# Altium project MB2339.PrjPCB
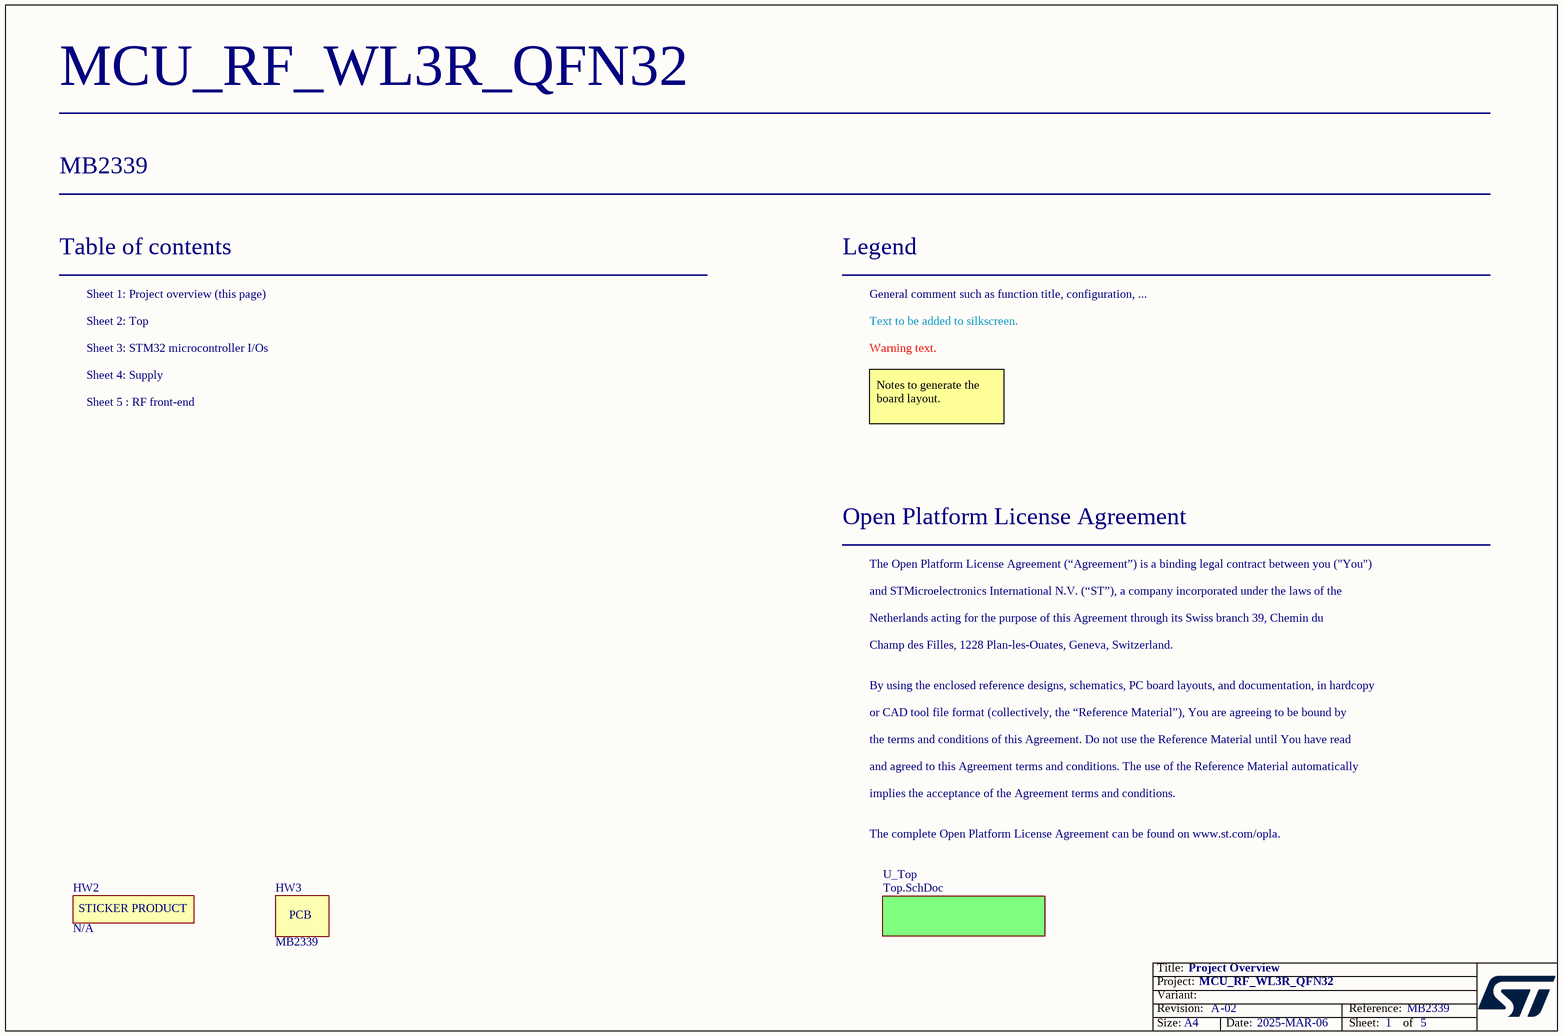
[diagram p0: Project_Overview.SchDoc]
Board_Assembly_Revision: 02; Board_Document_Date: 2025-MAR-06; Board_Name: MCU_RF_WL3R_QFN32; Board_PCB_Revision: A; Board_Reference: MB2339
5 sheets, 95 parts. Net scope: flat (ports and power ports of the same name join across sheets).
Board file: MB2339.PcbDoc
Sheets:
  Project_Overview.SchDoc
    U_Top = Top.SchDoc
      Designator = MCU_IOs.SchDoc
      Designator = RF.SchDoc
      Designator = Supply.SchDoc

## Sheet Project_Overview.SchDoc: Project Overview
size A4; Date: Not used; ApprovedBy: Not used; CheckedBy: Not used; Author: Not used; CompanyName: STMicroelectronics; DrawnBy: Not used; Engineer: Not used; Organization: Not used; Address1: Not used; Address2: Not used; Address3: Not used; Address4: Not used; DocumentNumber: 1; Revision: Not used; SheetNumber: 1; SheetTotal: 5

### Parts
HW2  STICKER_PRODUCT  [STICKER_PRODUCT_25X9]  (value not drawn)  (no BOM)
HW3  value MB2339  (hidden comment: PCB)

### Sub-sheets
U_Top = Top.SchDoc: no entries

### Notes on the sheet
- Table of contents
- Sheet 1: Project overview (this page)
- Legend
- General comment such as function title, configuration, ...
- Sheet 2: Top
- Sheet 3: STM32 microcontroller I/Os
- Sheet 4: Supply
- Text to be added to silkscreen.
- Warning text.
- Sheet 5 : RF front-end
- Notes to generate the board layout.
- Open Platform License Agreement
- The Open Platform License Agreement (“Agreement”) is a binding legal contract between you ("You")
- and STMicroelectronics International N.V. (“ST”), a company incorporated under the laws of the
- Netherlands acting for the purpose of this Agreement through its Swiss branch 39, Chemin du
- Champ des Filles, 1228 Plan-les-Ouates, Geneva, Switzerland.
- By using the enclosed reference designs, schematics, PC board layouts, and documentation, in hardcopy
- or CAD tool file format (collectively, the “Reference Material”), You are agreeing to be bound by
- the terms and conditions of this Agreement. Do not use the Reference Material until You have read
- and agreed to this Agreement terms and conditions. The use of the Reference Material automatically
- implies the acceptance of the Agreement terms and conditions.
- The complete Open Platform License Agreement can be found on www.st.com/opla.

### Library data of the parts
HW2 = MCD-00547: Sticker product, 25x9mm; Part_Type: Misc; Part_Preference: Recommended; Component_Country_Of_Origin: Unknown; ShowFields: YES; ID: 3197
HW3 = MCD-04477: PCB, MB2339, STM32WL3R Nucleo, 4L2S; Part_Preference: Recommended; Manufacturer: WURTH ELEKTRONIK; Component_Country_Of_Origin: Unknown; ShowFields: YES; ID: 6593

## Sheet Top.SchDoc: Top Schematic
size A4; Date: Not used; ApprovedBy: Not used; CheckedBy: Not used; Author: Not used; CompanyName: STMicroelectronics; DrawnBy: Not used; Engineer: Not used; Organization: Not used; Address1: Not used; Address2: Not used; Address3: Not used; Address4: Not used; DocumentNumber: 2; Revision: Not used; SheetNumber: 2; SheetTotal: 5
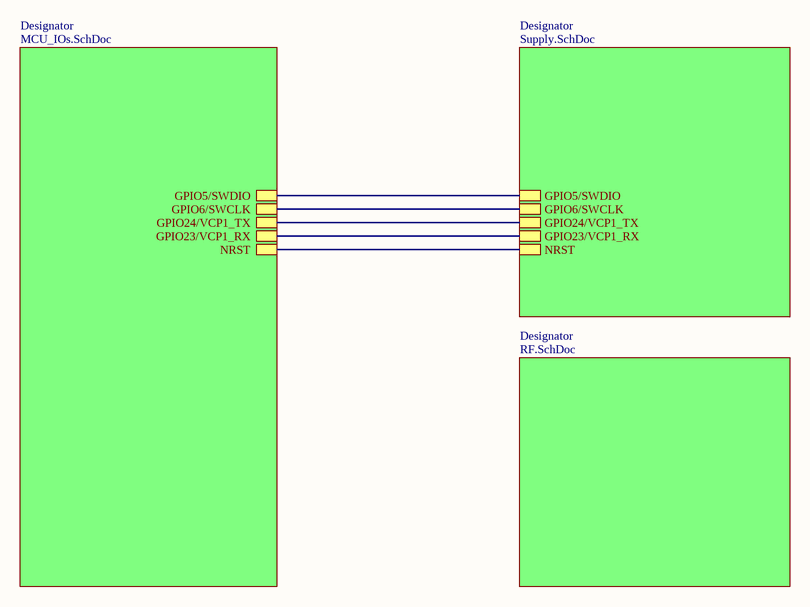
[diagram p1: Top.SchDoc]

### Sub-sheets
Designator = MCU_IOs.SchDoc: NRST, GPIO5/SWDIO, GPIO6/SWCLK, GPIO24/VCP1_TX, GPIO23/VCP1_RX
Designator = RF.SchDoc: no entries
Designator = Supply.SchDoc: NRST, GPIO5/SWDIO, GPIO6/SWCLK, GPIO23/VCP1_RX, GPIO24/VCP1_TX

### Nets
(unnamed): sheet Designator/NRST, sheet Designator/NRST
(unnamed): sheet Designator/GPIO5/SWDIO, sheet Designator/GPIO5/SWDIO  [a separate net that carries the same name]
(unnamed): sheet Designator/GPIO6/SWCLK, sheet Designator/GPIO6/SWCLK  [a separate net that carries the same name]
(unnamed): sheet Designator/GPIO24/VCP1_TX, sheet Designator/GPIO24/VCP1_TX  [a separate net that carries the same name]
(unnamed): sheet Designator/GPIO23/VCP1_RX, sheet Designator/GPIO23/VCP1_RX  [a separate net that carries the same name]

## Sheet MCU_IOs.SchDoc: STM32 I/Os & Clock
size A4; Date: Not used; ApprovedBy: Not used; CheckedBy: Not used; Author: Not used; CompanyName: STMicroelectronics; DrawnBy: Not used; Engineer: Not used; Organization: Not used; Address1: Not used; Address2: Not used; Address3: Not used; Address4: Not used; DocumentNumber: 3; Revision: Not used; SheetNumber: 3; SheetTotal: 5
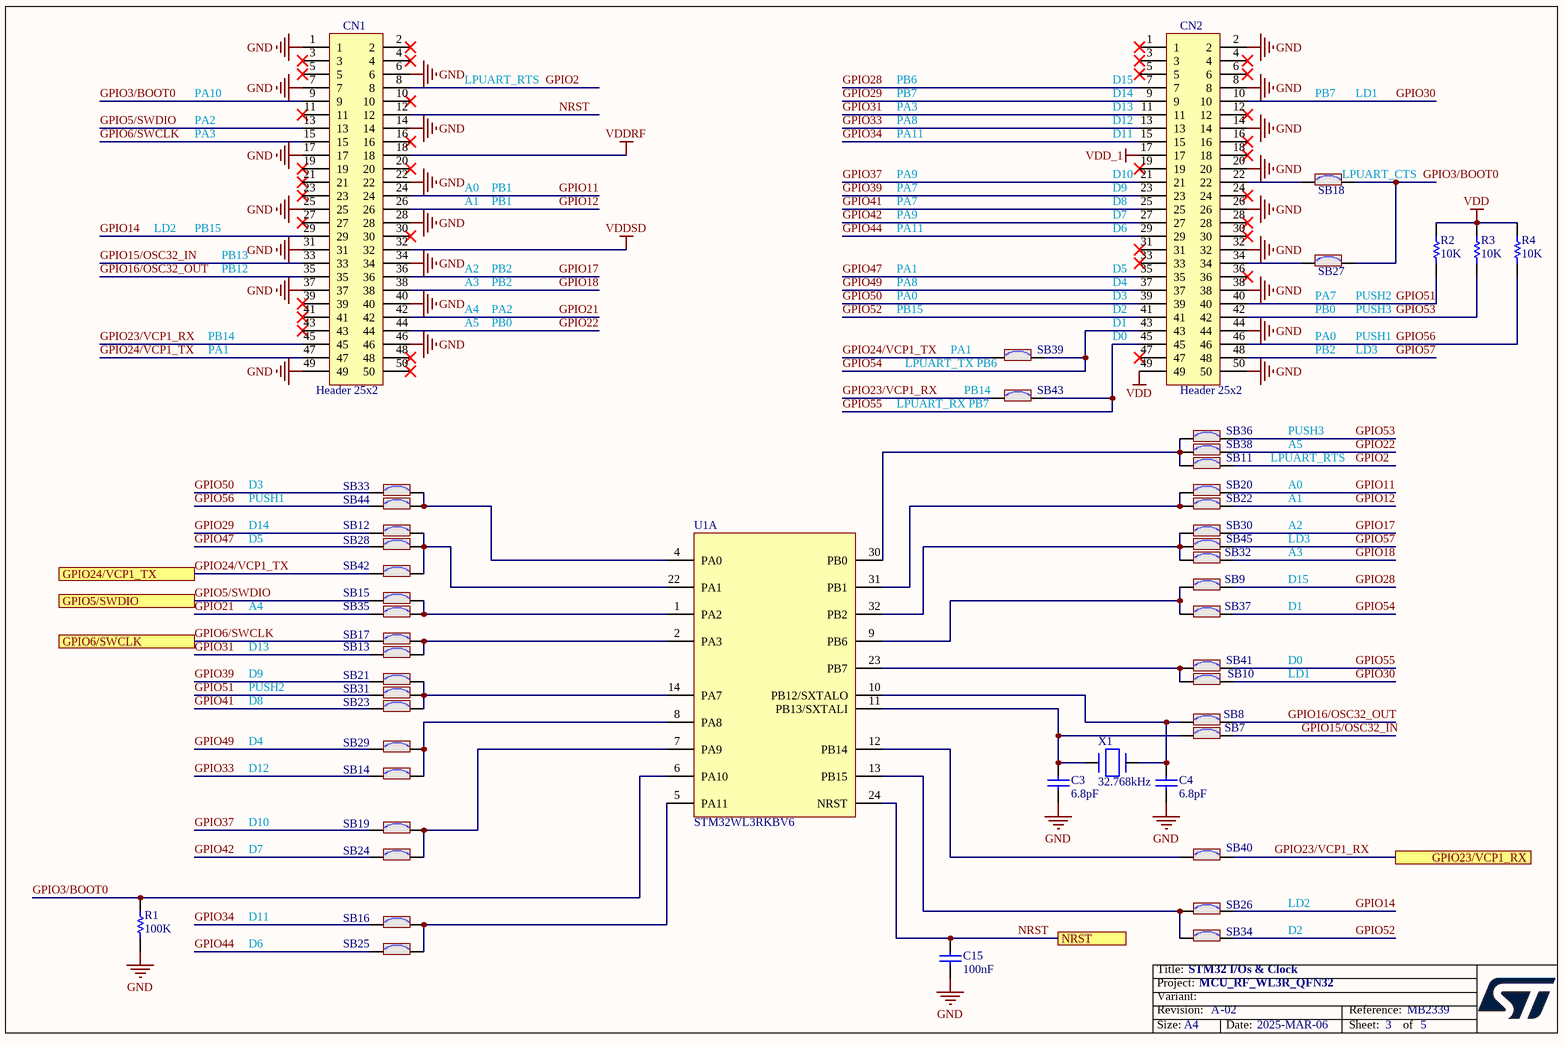
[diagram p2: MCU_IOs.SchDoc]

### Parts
C3  value 6.8pF  [C0402]  (hidden comment: Capacitor)
C4  value 6.8pF  [C0402]  (hidden comment: Capacitor)
C15  value 100nF  [C0402]  (hidden comment: Capacitor)
CN1  Header 25x2  [CON_SAMTEC_FTSH-125-02-L-DV]
CN2  Header 25x2  [CON_SAMTEC_FTSH-125-02-L-DV]
R1  value 100K  [R0402]  (hidden comment: Resistor)
R2  value 10K  [R0402]  (hidden comment: Resistor)
R3  value 10K  [R0402]  (hidden comment: Resistor)
R4  value 10K  [R0402]  (hidden comment: Resistor)
SB7  SB_ON  [SOLDER-BRIDGE_R0402-0R]  (value not drawn)
SB8  SB_ON  [SOLDER-BRIDGE_R0402-0R]  (value not drawn)
SB9  SB_ON  [SOLDER-BRIDGE_R0402-0R]  (value not drawn)
SB10  SB_ON  [SOLDER-BRIDGE_R0402-0R]  (value not drawn)
SB11  SB_ON  [SOLDER-BRIDGE_R0402-0R]  (value not drawn)
SB12  SB_ON  [SOLDER-BRIDGE_R0402-0R]  (value not drawn)
SB13  SB_ON  [SOLDER-BRIDGE_R0402-0R]  (value not drawn)
SB14  SB_ON  [SOLDER-BRIDGE_R0402-0R]  (value not drawn)
SB15  SB_ON  [SOLDER-BRIDGE_R0402-0R]  (value not drawn)
SB16  SB_ON  [SOLDER-BRIDGE_R0402-0R]  (value not drawn)
SB17  SB_ON  [SOLDER-BRIDGE_R0402-0R]  (value not drawn)
SB18  SB_ON  [SOLDER-BRIDGE_R0402-0R]  (value not drawn)
SB19  SB_ON  [SOLDER-BRIDGE_R0402-0R]  (value not drawn)
SB20  SB_ON  [SOLDER-BRIDGE_R0402-0R]  (value not drawn)
SB21  SB_ON  [SOLDER-BRIDGE_R0402-0R]  (value not drawn)
SB22  SB_ON  [SOLDER-BRIDGE_R0402-0R]  (value not drawn)
SB23  SB_ON  [SOLDER-BRIDGE_R0402-0R]  (value not drawn)
SB24  SB_ON  [SOLDER-BRIDGE_R0402-0R]  (value not drawn)
SB25  SB_ON  [SOLDER-BRIDGE_R0402-0R]  (value not drawn)
SB26  SB_ON  [SOLDER-BRIDGE_R0402-0R]  (value not drawn)
SB27  SB_ON  [SOLDER-BRIDGE_R0402-0R]  (value not drawn)
SB28  SB_ON  [SOLDER-BRIDGE_R0402-0R]  (value not drawn)
SB29  SB_ON  [SOLDER-BRIDGE_R0402-0R]  (value not drawn)
SB30  SB_ON  [SOLDER-BRIDGE_R0402-0R]  (value not drawn)
SB31  SB_ON  [SOLDER-BRIDGE_R0402-0R]  (value not drawn)
SB32  SB_ON  [SOLDER-BRIDGE_R0402-0R]  (value not drawn)
SB33  SB_ON  [SOLDER-BRIDGE_R0402-0R]  (value not drawn)
SB34  SB_ON  [SOLDER-BRIDGE_R0402-0R]  (value not drawn)
SB35  SB_ON  [SOLDER-BRIDGE_R0402-0R]  (value not drawn)
SB36  SB_ON  [SOLDER-BRIDGE_R0402-0R]  (value not drawn)
SB37  SB_ON  [SOLDER-BRIDGE_R0402-0R]  (value not drawn)
SB38  SB_ON  [SOLDER-BRIDGE_R0402-0R]  (value not drawn)
SB39  SB_ON  [SOLDER-BRIDGE_R0402-0R]  (value not drawn)
SB40  SB_ON  [SOLDER-BRIDGE_R0402-0R]  (value not drawn)
SB41  SB_ON  [SOLDER-BRIDGE_R0402-0R]  (value not drawn)
SB42  SB_ON  [SOLDER-BRIDGE_R0402-0R]  (value not drawn)
SB43  SB_ON  [SOLDER-BRIDGE_R0402-0R]  (value not drawn)
SB44  SB_ON  [SOLDER-BRIDGE_R0402-0R]  (value not drawn)
SB45  SB_ON  [SOLDER-BRIDGE_R0402-0R]  (value not drawn)
U1  value STM32WL3RKBV6  [ICC_VFQFPN32-EPAD_5X5_P050]  (hidden comment: IC_STM32WL3R)  (part A of 3)
X1  value 32.768kHz  [CRY_NX2012SA_2P]  (hidden comment: XTAL_2_PINS)

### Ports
GPIO5/SWDIO, GPIO6/SWCLK, GPIO23/VCP1_RX, GPIO24/VCP1_TX, NRST

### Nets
GND: C3.1 C4.2 C15.1 CN1.1 CN1.6 CN1.7 CN1.14 CN1.17 CN1.22 CN1.25 CN1.28 CN1.31 CN1.34 CN1.37 CN1.40 CN1.46 CN1.49 CN2.2 CN2.8 CN2.14 CN2.20 CN2.26 CN2.32 CN2.38 CN2.44 CN2.50 R1.1
VDD: CN2.49 R2.2 R3.2 R4.2
VDD_1: CN2.17
VDDRF: CN1.18
VDDSD: CN1.32
GPIO2: CN1.8 SB11.2
GPIO3/BOOT0: CN1.9 R1.2 SB18.2 SB27.2 U1.6(PA10)
GPIO5/SWDIO: CN1.13 SB15.1 ; port GPIO5/SWDIO
GPIO6/SWCLK: CN1.15 SB17.1 ; port GPIO6/SWCLK
GPIO11: CN1.24 SB20.2
GPIO12: CN1.26 SB22.2
GPIO14: CN1.29 SB26.2
GPIO15/OSC32_IN: CN1.33 SB7.2
GPIO16/OSC32_OUT: CN1.35 SB8.2
GPIO17: CN1.36 SB30.2
GPIO18: CN1.38 SB32.2
GPIO21: CN1.42 SB35.1
GPIO22: CN1.44 SB38.2
GPIO23/VCP1_RX: CN1.45 SB40.2 SB43.1 ; port GPIO23/VCP1_RX
GPIO24/VCP1_TX: CN1.47 SB39.1 SB42.1 ; port GPIO24/VCP1_TX
GPIO28: CN2.7 SB9.2
GPIO29: CN2.9 SB12.1
GPIO30: CN2.10 SB10.2
GPIO31: CN2.11 SB13.1
GPIO33: CN2.13 SB14.1
GPIO34: CN2.15 SB16.1
GPIO37: CN2.21 SB19.1
GPIO39: CN2.23 SB21.1
GPIO41: CN2.25 SB23.1
GPIO42: CN2.27 SB24.1
GPIO44: CN2.29 SB25.1
GPIO47: CN2.35 SB28.1
GPIO49: CN2.37 SB29.1
GPIO50: CN2.39 SB33.1
GPIO51: CN2.40 R2.1 SB31.1
GPIO52: CN2.41 SB34.2
GPIO53: CN2.42 R3.1 SB36.2
GPIO54: CN2.43 SB37.2 SB39.2
GPIO55: CN2.45 SB41.2 SB43.2
GPIO56: CN2.46 R4.1 SB44.1
GPIO57: CN2.48 SB45.2
NRST: C15.2 CN1.12 U1.24(NRST) ; port NRST
NetC3_2: C3.2 SB7.1 U1.11(PB13/SXTALI) X1.1(X1)
NetC4_1: C4.1 SB8.1 U1.10(PB12/SXTALO) X1.2(X2)
NetCN2_22: CN2.22 SB18.1
NetCN2_34: CN2.34 SB27.1
NetSB9_1: SB9.1 SB37.1 U1.9(PB6)
NetSB10_1: SB10.1 SB41.1 U1.23(PB7)
NetSB11_1: SB11.1 SB36.1 SB38.1 U1.30(PB0)
NetSB12_2: SB12.2 SB28.2 SB42.2 U1.22(PA1)
NetSB13_2: SB13.2 SB17.2 U1.2(PA3)
NetSB14_2: SB14.2 SB29.2 U1.8(PA8)
NetSB15_2: SB15.2 SB35.2 U1.1(PA2)
NetSB16_2: SB16.2 SB25.2 U1.5(PA11)
NetSB19_2: SB19.2 SB24.2 U1.7(PA9)
NetSB20_1: SB20.1 SB22.1 U1.31(PB1)
NetSB21_2: SB21.2 SB23.2 SB31.2 U1.14(PA7)
NetSB26_1: SB26.1 SB34.1 U1.13(PB15)
NetSB30_1: SB30.1 SB32.1 SB45.1 U1.32(PB2)
NetSB33_2: SB33.2 SB44.2 U1.4(PA0)
NetSB40_1: SB40.1 U1.12(PB14)

Not connected (* = marked no-connect by the designer): CN1 2* 3* 4* 5* 10* 11* 16* 19* 20* 21* 23* 27* 30* 39* 41* 43* 48* 50*; CN2 1* 3* 4* 5* 6* 12* 16* 18* 19* 24* 28* 30* 31* 33* 36* 47*

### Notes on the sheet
- PA10
- LPUART_RTS
- PB7
- PB6
- PA3
- (near CN2) D13
- (near CN2) D14
- (near CN2) D15
- LD1
- PA2
- PA8
- PA11
- PA9
- (near CN2) D11
- (near CN2) D12
- (near CN2) D10
- (near SB18) LPUART_CTS
- LD2
- PB15
- A0
- A1
- PB1
- PA7
- (near CN2) D9
- (near CN2) D8
- (near CN2) D7
- (near CN2) D6
- PB13
- PB12
- A4
- A3
- A2
- PB2
- PA1
- PA0
- (near CN2) D5
- (near CN2) D4
- (near CN2) D3
- (near CN2) D2
- (near SB27) PA7
- (near SB27) PB0
- (near SB27) PUSH2
- PUSH3
- PB14
- A5
- PB0
- LPUART_TX PB6
- (near CN2) D1
- (near CN2) D0
- LD3
- PUSH1
- (near SB43) LPUART_RX PB7
- (near SB43) PB14
- D3
- D14
- D5
- D15
- D13
- D1
- D8
- PUSH2
- D9
- D0
- D4
- D12
- D7
- D10
- D11
- D6
- D2

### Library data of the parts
C3 C4 = MCD-03452: Capacitor, MLCC, 6.8pF, 50V,C0G/NP0, +/-0.05pF, 0402, T=0.5mm; Part_Preference: Recommended; Manufacturer: MURATA; Manufacturer_Part_Number: GJM1555C1H6R8WB01; ShowFields: YES; ID: 5568; Component_Country_Of_Origin: Japan, Singapore
C15 = MCD-00006: Capacitor, MLCC, 100nF, 16V, X7R, +/-10%, 0402, T=0.5mm; Manufacturer_Part_Number: CC0402KRX7R7BB104; Manufacturer: YAGEO; Part_Preference: Recommended; Partial_Alternate_Internal_Part_Number: MCD-03299; Order_Code_RS: 9402047; Component_Country_Of_Origin: China; ShowFields: YES; ID: 2474
CN1 CN2 = MCD-02746: Header, 25x2, 1.27mm, VR, SMD, T=4.83mm; Part_Type: Connector; Part_Preference: Recommended; Manufacturer: SAMTEC; Manufacturer_Part_Number: FTSH-125-02-L-DV; Partial_Alternate_Internal_Part_Number: MCD-03741; ShowFields: YES; ID: 4858; Component_Country_Of_Origin: China, Costa Rica, Malaysia, USA, Vietnam
R1 = MCD-00059: Resistor, 100K, 0402, +/-1%, 1/16W; Part_Preference: Recommended; Manufacturer: YAGEO; Manufacturer_Part_Number: RC0402FR-07100KL; Partial_Alternate_Internal_Part_Number: MCD-03301; Order_Code_RS: 2421891; ShowFields: YES; ID: 2533; Component_Country_Of_Origin: China
R2-R4 = MCD-00053: Resistor, 10K, 0402, +/-1%, 1/16W; BMS_Part_Number: 9131590; Part_Preference: Recommended; Manufacturer: YAGEO; Manufacturer_Part_Number: RC0402FR-0710KL; Order_Code_RS: 9239359; Component_Country_Of_Origin: China; ShowFields: YES; ID: 2539
SB7-SB45 = MCD-01618: Resistor, 0R, SB0402, 5%, 0.063W; Part_Preference: Recommended; Manufacturer: YAGEO; Manufacturer_Part_Number: RC0402JR-070RL; Order_Code_RS: 618-5804; Component_Country_Of_Origin: China; ShowFields: YES; ID: 3718
U1 = MCD-04431: MCU, ARM Cortex-M0 32-bit, 128KB Flash, 16KB SRAM, With Crypto; Part_Type: IC; Part_Preference: Recommended; Manufacturer: STMICROELECTRONICS; ShowFields: YES; ID: 6547; Component_Country_Of_Origin: Unknown
X1 = MCD-01445: Crystal, 32.768kHz, 7pF, +/-20ppm, 80K, 2.05x1.2mm; BMS_Part_Number: 9157043; Part_Type: Crystal_Osc; Part_Preference: Recommended; Manufacturer: NDK; Manufacturer_Part_Number: NX2012SA-32.768KHz-EXS00A-MU00389; Component_Country_Of_Origin: Japan; ShowFields: YES; ID: 3545

## Sheet RF.SchDoc: STM32 RF
size A4; Date: Not used; ApprovedBy: Not used; CheckedBy: Not used; Author: Not used; CompanyName: STMicroelectronics; DrawnBy: Not used; Engineer: Not used; Organization: Not used; Address1: Not used; Address2: Not used; Address3: Not used; Address4: Not used; DocumentNumber: 5; Revision: Not used; SheetNumber: 5; SheetTotal: 5
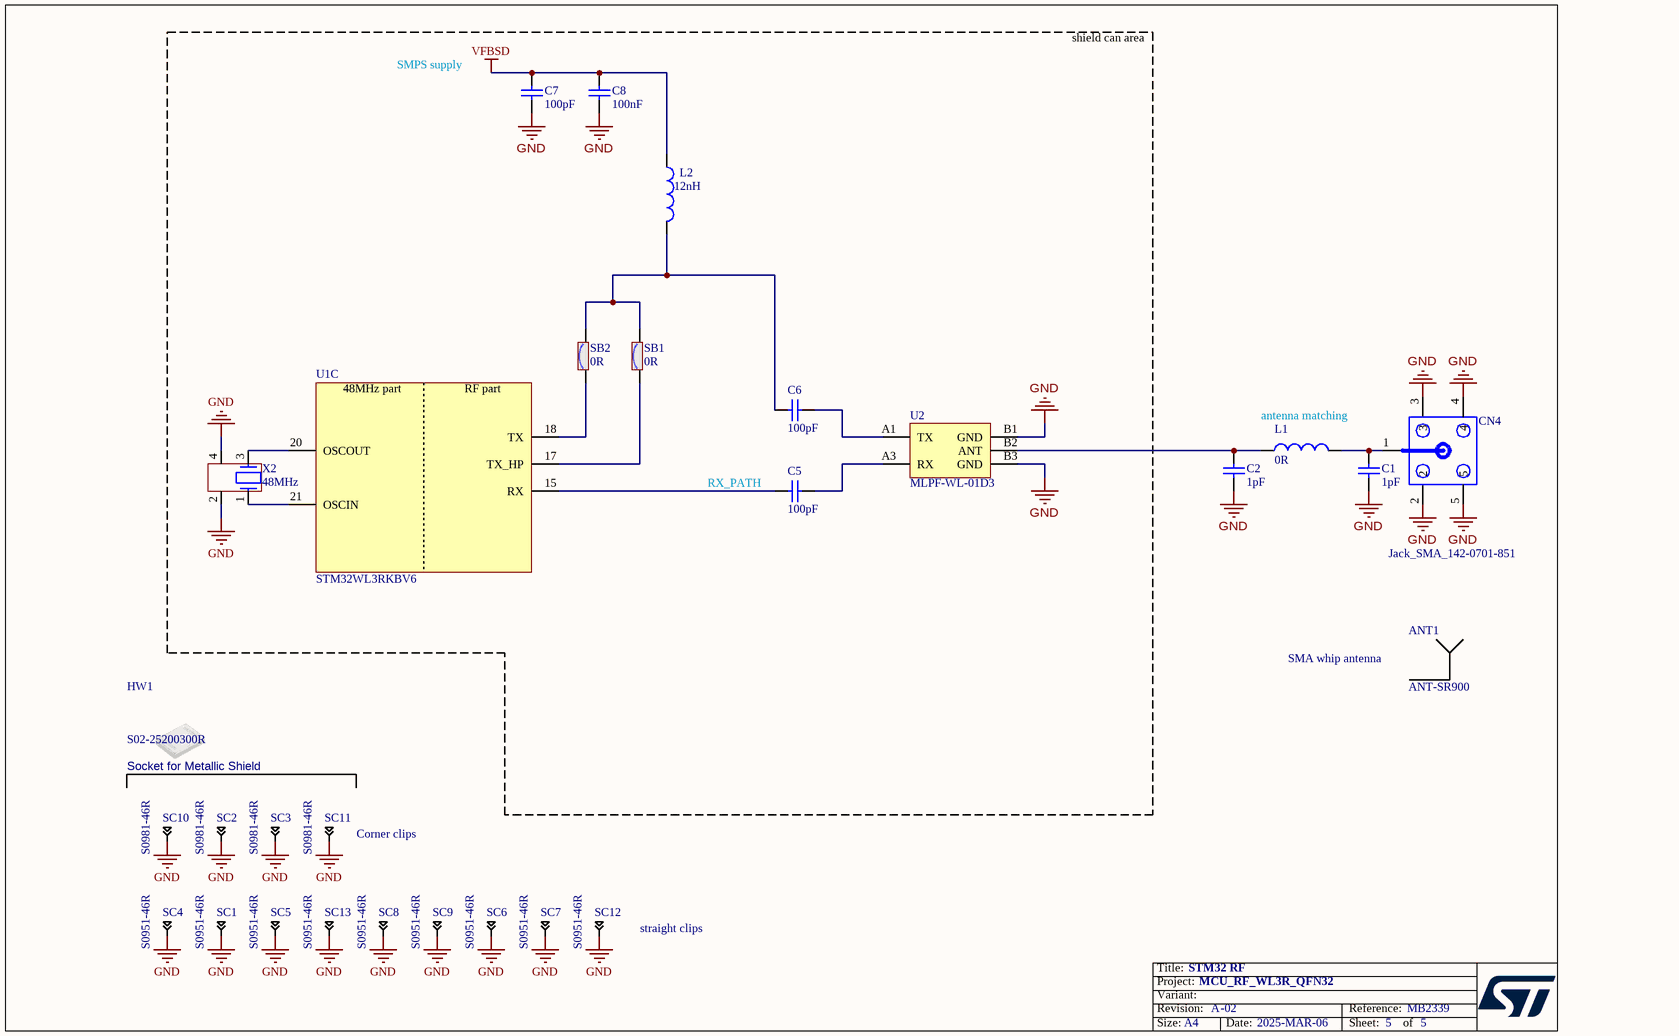
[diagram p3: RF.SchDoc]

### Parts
ANT1  value ANT-SR900  (hidden comment: ANT)
C1  value 1pF  [C0402]  (hidden comment: Capacitor)
C2  value 1pF  [C0402]  (hidden comment: Capacitor)
C5  value 100pF  [C0402]  (hidden comment: Capacitor)
C6  value 100pF  [C0402]  (hidden comment: Capacitor)
C7  value 100pF  [C0402]  (hidden comment: Capacitor)
C8  value 100nF  [C0402]  (hidden comment: Capacitor)
CN4  value Jack_SMA_142-0701-851  [CON_SMA-RF_CINCH_142-0701-851]  (hidden comment: mmcx)
HW1  value S02-25200300R  [SHIELD_HARWIN_S02-25200300_20X25_H3]  (hidden comment: S02-20150300)
L1  value 0R  [IND_0402_MURATA_LQW15AN_H0P5]  (hidden comment: Inductor)
L2  value 12nH  [IND_0402_MURATA_LQW15ANXXXX00_H0P5]  (hidden comment: Inductor)
SB1  value 0R  [SOLDER-BRIDGE_R0201_0R]  (hidden comment: SB_ON)
SB2  value 0R  [SOLDER-BRIDGE_R0201_0R]  (hidden comment: SB_ON)
SC1  value S0951-46R  [CLIP_HARWIN_S0951-46R]  (hidden comment: Shield-clip_S0951-46R)
SC2  value S0981-46R  [CLIP_HARWIN_S0981-46R]  (hidden comment: Shield-clip_S0951-46R)
SC3  value S0981-46R  [CLIP_HARWIN_S0981-46R]  (hidden comment: Shield-clip_S0951-46R)
SC4  value S0951-46R  [CLIP_HARWIN_S0951-46R]  (hidden comment: Shield-clip_S0951-46R)
SC5  value S0951-46R  [CLIP_HARWIN_S0951-46R]  (hidden comment: Shield-clip_S0951-46R)
SC6  value S0951-46R  [CLIP_HARWIN_S0951-46R]  (hidden comment: Shield-clip_S0951-46R)
SC7  value S0951-46R  [CLIP_HARWIN_S0951-46R]  (hidden comment: Shield-clip_S0951-46R)
SC8  value S0951-46R  [CLIP_HARWIN_S0951-46R]  (hidden comment: Shield-clip_S0951-46R)
SC9  value S0951-46R  [CLIP_HARWIN_S0951-46R]  (hidden comment: Shield-clip_S0951-46R)
SC10  value S0981-46R  [CLIP_HARWIN_S0981-46R]  (hidden comment: Shield-clip_S0951-46R)
SC11  value S0981-46R  [CLIP_HARWIN_S0981-46R]  (hidden comment: Shield-clip_S0951-46R)
SC12  value S0951-46R  [CLIP_HARWIN_S0951-46R]  (hidden comment: Shield-clip_S0951-46R)
SC13  value S0951-46R  [CLIP_HARWIN_S0951-46R]  (hidden comment: Shield-clip_S0951-46R)
U1  value STM32WL3RKBV6  [ICC_VFQFPN32-EPAD_5X5_P050]  (hidden comment: IC_STM32WL3R)  (part C of 3)
U2  value MLPF-WL-01D3  [ICC_CSPG5_1P5X1P9_P060]  (hidden comment: MLPF-WL-0xD3)
X2  value 48MHz  [CRY_NX1612SA_4P]  (hidden comment: XTAL_4_PINS)

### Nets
GND: C1.1 C2.1 C7.2 C8.1 CN4.2 CN4.3 CN4.4 CN4.5 SC1.1 SC2.1 SC3.1 SC4.1 SC5.1 SC6.1 SC7.1 SC8.1 SC9.1 SC10.1 SC11.1 SC12.1 SC13.1 U2.B1(GND) U2.B3(GND) X2.2 X2.4
VFBSD: C7.1 C8.2 L2.1
NetC1_2: C1.2 CN4.1 L1.2
NetC2_2: C2.2 L1.1 U2.B2(ANT)
NetC5_1: C5.1 U1.15(RX)
NetC5_2: C5.2 U2.A3(RX)
NetC6_1: C6.1 U2.A1(TX)
NetC6_2: C6.2 L2.2 SB1.2 SB2.2
NetSB1_1: SB1.1 U1.17(TX_HP)
NetSB2_1: SB2.1 U1.18(TX)
NetU1_20: U1.20(OSCOUT) X2.3
NetU1_21: U1.21(OSCIN) X2.1

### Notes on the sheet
- shield can area
- SMPS supply
- antenna matching
- (near C5) RX_PATH
- SMA whip antenna
- Socket for Metallic Shield
- (near SC11) Corner clips
- (near SC12) straight clips

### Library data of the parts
ANT1 = MCD-03598: Antenna, 868MHz To 915MHz, Compressed whip, SMA right angle; Part_Type: Misc; Part_Preference: Recommended; Manufacturer: LPRS; Component_Country_Of_Origin: China°; ShowFields: YES; ID: 5714
C1 C2 = MCD-01600: Capacitor, MLCC, 1pF, 50V, C0G/NP0, +/-0.1pF, 0402, T=0.5mm; Part_Preference: Recommended; Manufacturer: YAGEO; Manufacturer_Part_Number: CC0402BRNPO9BN1R0; Component_Country_Of_Origin: China; ShowFields: YES; ID: 3700
C5 = MCD-03446: Capacitor, MLCC, 100pF, 50V, C0G/NP0, +/-1%, 0402, T=0.5mm; Part_Preference: Recommended; Manufacturer: MURATA; Manufacturer_Part_Number: GCM1555C1H101FA16; Order_Code_RS: 247-7780; Component_Country_Of_Origin: China, Japan, Philippines, Singapore; ShowFields: YES; ID: 5562
C6 C7 = MCD-03446: Capacitor, MLCC, 100pF, 50V, C0G/NP0, +/-1%, 0402, T=0.5mm; Part_Preference: Recommended; Manufacturer: MURATA; Manufacturer_Part_Number: GCM1555C1H101FA16; Order_Code_RS: 247-7780; ShowFields: YES; ID: 5562; Component_Country_Of_Origin: China, Japan, Philippines, Singapore
C8 = MCD-03442: Capacitor, MLCC, 100nF, 25V, X7R, +/-10%, 0402, T=0.5mm; Part_Preference: Recommended; Manufacturer: MURATA; Manufacturer_Part_Number: GRM155R71E104KE14; Order_Code_RS: 247-8011; ShowFields: YES; ID: 5558; Component_Country_Of_Origin: China, Japan, Philippines, Singapore
CN4 = MCD-02072: Jack_SMA, VR, PCB edge, 50R, T=7.92mm; Part_Type: Connector; Part_Preference: Forbidden; Manufacturer: CINCH; Manufacturer_Part_Number: 142-0701-851; Order_Code_RS: 885-7532; Component_Country_Of_Origin: USA°°; ShowFields: YES; ID: 4172
HW1 = MCD-03503: RFI shield CAN, 25x20x3mm; Part_Type: Misc; Part_Preference: Recommended; Manufacturer: HARWIN; Order_Code_RS: 247-9197; Component_Country_Of_Origin: UK; ShowFields: YES; ID: 5619
L1 = MCD-01937: Resistor, 0R, 0402, +/-5%, 1/16W; Part_Preference: Recommended; Manufacturer: YAGEO; Manufacturer_Part_Number: RC0402JR-070RL; Order_Code_RS: 618-5804; Component_Country_Of_Origin: China; ShowFields: YES; ID: 4037
L2 = MCD-03456: Inductor, 12nH, +/-2%, 500mA, 0R14, 0402, T=0.5mm; Part_Preference: Recommended; Manufacturer: MURATA; Manufacturer_Part_Number: LQW15AN12NG00D; Order_Code_RS: 124-8172; ShowFields: YES; ID: 5572; Component_Country_Of_Origin: Japan, Malaysia
SB1 SB2 = MCD-03219: Solder Bridge ON, 0R, 0201, 1/20W; Part_Type: Misc; Part_Preference: Recommended; Manufacturer: YAGEO; Manufacturer_Part_Number: RC0201JR-070RL; Order_Code_RS: 198-7623; Component_Country_Of_Origin: China; ShowFields: YES; ID: 5335
SC1 SC4-SC9 SC12 SC13 = MCD-01587: RFI shield clip mini TIN SMD; Part_Type: Mechanical; Part_Preference: Recommended; Manufacturer: HARWIN; Component_Country_Of_Origin: Korea; ShowFields: YES; ID: 3687
SC2 SC3 SC10 SC11 = MCD-02164: Shield clip Harwin S0981-46R to fix RF shielded cavity; Part_Type: Mechanical; Part_Preference: Recommended; Order_Code_RS: 161-3702; Component_Country_Of_Origin: Korea; ShowFields: YES; ID: 4264
U1 = MCD-04431: as U1 on sheet MCU_IOs
U2 = MCD-03962: IC, 862 To 928MHz,16dBm, 4L PCB, IPD for STM32WL3; Part_Preference: Recommended; Manufacturer: STMICROELECTRONICS; ShowFields: YES; ID: 6078; Component_Country_Of_Origin: Unknown
X2 = MCD-03559: Crystal, 48MHz, 8pF, +/-10ppm, 80R, 1.6x1.2mm; Part_Type: Crystal_Osc; Part_Preference: Recommended; Manufacturer: NDK; Manufacturer_Part_Number: NX1612SA-48.000MHz-EXS00A-CS12140; ShowFields: YES; ID: 5675; Component_Country_Of_Origin: Japan

## Sheet Supply.SchDoc: STM32 power
size A4; Date: Not used; ApprovedBy: Not used; CheckedBy: Not used; Author: Not used; CompanyName: STMicroelectronics; DrawnBy: Not used; Engineer: Not used; Organization: Not used; Address1: Not used; Address2: Not used; Address3: Not used; Address4: Not used; DocumentNumber: 4; Revision: Not used; SheetNumber: 4; SheetTotal: 5
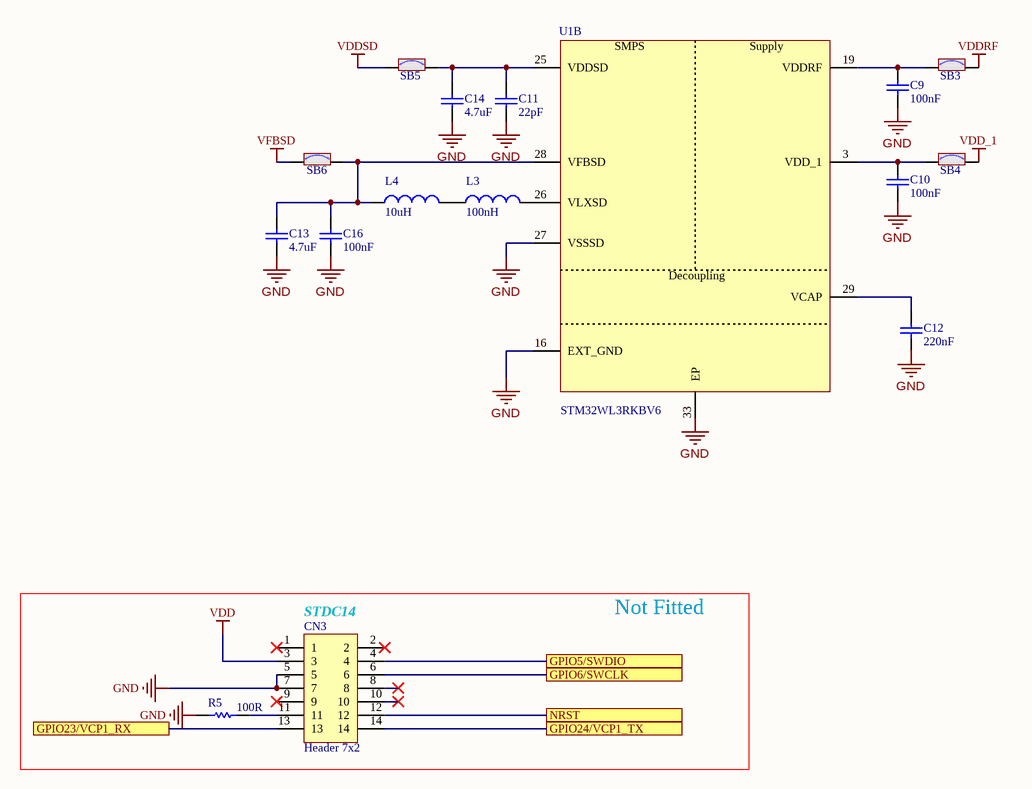
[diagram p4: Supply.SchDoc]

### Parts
C9  value 100nF  [C0402]  (hidden comment: Capacitor)
C10  value 100nF  [C0402]  (hidden comment: Capacitor)
C11  value 22pF  [C0402_H0P5]  (hidden comment: Capacitor)
C12  value 220nF  [C0402]  (hidden comment: Capacitor)
C13  value 4.7uF  [C0402]  (hidden comment: Capacitor)
C14  value 4.7uF  [C0402]  (hidden comment: Capacitor)
C16  value 100nF  [C0402]  (hidden comment: Capacitor)
CN3  Header 7x2  [CON_SAMTEC_FTSH-107-01-L-DV-K-A]
L3  value 100nH  [IND_0402_MURATA_LQG15HSXXXX02_H0P5]  (hidden comment: Inductor)
L4  value 10uH  [IND_0805_MURATA_LQM21]  (hidden comment: Inductor)
R5  value 100R  [R0402]  (hidden comment: Resistor)
SB3  SB_ON  [SOLDER-BRIDGE_R0402-0R]  (value not drawn)
SB4  SB_ON  [SOLDER-BRIDGE_R0402-0R]  (value not drawn)
SB5  SB_ON  [SOLDER-BRIDGE_R0402-0R]  (value not drawn)
SB6  SB_ON  [SOLDER-BRIDGE_R0402-0R]  (value not drawn)
U1  value STM32WL3RKBV6  [ICC_VFQFPN32-EPAD_5X5_P050]  (hidden comment: IC_STM32WL3R)  (part B of 3)

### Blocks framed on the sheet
Not Fitted: CN3 R5

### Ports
GPIO5/SWDIO, GPIO6/SWCLK, GPIO23/VCP1_RX, GPIO24/VCP1_TX, NRST

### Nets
GND: C9.1 C10.1 C11.2 C12.1 C13.1 C14.1 C16.2 CN3.5 CN3.7 R5.1 U1.16(EXT_GND) U1.27(VSSSD) U1.33(EP)
VDD: CN3.3
VDD_1: SB4.2
VDDRF: SB3.2
VDDSD: SB5.1
VFBSD: SB6.1
GPIO5/SWDIO: CN3.4 ; port GPIO5/SWDIO
GPIO6/SWCLK: CN3.6 ; port GPIO6/SWCLK
GPIO23/VCP1_RX: CN3.13 ; port GPIO23/VCP1_RX
GPIO24/VCP1_TX: CN3.14 ; port GPIO24/VCP1_TX
NRST: CN3.12 ; port NRST
NetC9_2: C9.2 SB3.1 U1.19(VDDRF)
NetC10_2: C10.2 SB4.1 U1.3(VDD_1)
NetC11_1: C11.1 C14.2 SB5.2 U1.25(VDDSD)
NetC12_2: C12.2 U1.29(VCAP)
NetC13_2: C13.2 C16.1 L4.1 SB6.2 U1.28(VFBSD)
NetCN3_11: CN3.11 R5.2
NetL3_1: L3.1 L4.2
NetL3_2: L3.2 U1.26(VLXSD)

Not connected (* = marked no-connect by the designer): CN3 1* 2* 8* 9* 10*

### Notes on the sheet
- (near CN3) STDC14

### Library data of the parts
C9 C10 C16 = MCD-03442: Capacitor, MLCC, 100nF, 25V, X7R, +/-10%, 0402, T=0.5mm; Part_Preference: Recommended; Manufacturer: MURATA; Manufacturer_Part_Number: GRM155R71E104KE14D; Order_Code_RS: 247-8011; ShowFields: YES; ID: 5558; Component_Country_Of_Origin: China, Japan, Philippines, Singapore
C11 = MCD-03948: Capacitor, MLCC, 22pF, 50V, C0G, +/-5%, 0402, T=0.5mm; Part_Preference: Recommended; Manufacturer: MURATA; Manufacturer_Part_Number: GJM1555C1H220JB01; Order_Code_RS: 185-3422; ShowFields: YES; ID: 6064; Component_Country_Of_Origin: Japan, Singapore
C12 = MCD-03077: Capacitor, MLCC, 220nF, 35V, X6S, +/-10%, 0402, T=0.5mm; Part_Preference: Recommended; Manufacturer: MURATA; Manufacturer_Part_Number: GRM155C8YA224KE01D; Component_Country_Of_Origin: Japan; ShowFields: YES; ID: 5193
C13 C14 = MCD-03431: Capacitor, MLCC, 4.7uF, 10V, X5R, +/-20%, 0402, T=0.5mm; Part_Preference: Recommended; Manufacturer: MURATA; Manufacturer_Part_Number: GRM155R61A475MEAAD; Order_Code_RS: 172-6870; ShowFields: YES; ID: 5547; Component_Country_Of_Origin: China, Japan, Philippines, Singapore
CN3 = MCD-01531: Header, 7x2, 1.27mm, VR, T=5.97mm, FTSH series STDC14 without Alignment Pin; Part_Type: Connector; Part_Preference: Recommended; Manufacturer: SAMTEC; Manufacturer_Part_Number: FTSH-107-01-L-DV-K; Order_Code_RS: 179-9021; Component_Country_Of_Origin: China, Costa Rica, Malaysia, USA, Vietnam; ShowFields: YES; ID: 3631
L3 = MCD-03453: Inductor, 100nH, +/-5%, 200mA, 1R25, 0402, T=0.5mm; Part_Preference: Recommended; Manufacturer: MURATA; Manufacturer_Part_Number: LQG15HSR10J02; Order_Code_RS: 792-6369; ShowFields: YES; ID: 5569; Component_Country_Of_Origin: Japan
L4 = MCD-02317: Inductor, 10uH, +/-20%, 100mA, 0R5, 0805, T=1.45mm; Part_Preference: Recommended; Manufacturer: MURATA; Manufacturer_Part_Number: LQM21FN100M80L; Order_Code_RS: 786-7074; Component_Country_Of_Origin: Japan°°; ShowFields: YES; ID: 4423
R5 = MCD-00067: Resistor, 100R, 0402, +/- 1%, 1/16W; Part_Preference: Recommended; Manufacturer: YAGEO; Manufacturer_Part_Number: RC0402FR-07100RL; Order_Code_RS: 9239111; Component_Country_Of_Origin: China; ShowFields: YES; ID: 2527
SB3-SB6 = MCD-01618: as SB7 on sheet MCU_IOs
U1 = MCD-04431: MCU, ARM Cortex-M0 32-bit, 128KB Flash, 16KB SRAM, With Crypto; Part_Type: IC; Part_Preference: Recommended; Manufacturer: STMICROELECTRONICS; ShowFields: YES; ID: 6547

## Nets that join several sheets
GND: MCU_IOs (27 pins), RF (25 pins), Supply (13 pins)
VDD: MCU_IOs (CN2.49 R2.2 R3.2 R4.2), Supply (CN3.3)
VDD_1: MCU_IOs (CN2.17), Supply (SB4.2)
VDDRF: MCU_IOs (CN1.18), Supply (SB3.2)
VDDSD: MCU_IOs (CN1.32), Supply (SB5.1)
VFBSD: RF (C7.1 C8.2 L2.1), Supply (SB6.1)
GPIO5/SWDIO: MCU_IOs (CN1.13 SB15.1), Supply (CN3.4)
GPIO6/SWCLK: MCU_IOs (CN1.15 SB17.1), Supply (CN3.6)
GPIO23/VCP1_RX: MCU_IOs (CN1.45 SB40.2 SB43.1), Supply (CN3.13)
GPIO24/VCP1_TX: MCU_IOs (CN1.47 SB39.1 SB42.1), Supply (CN3.14)
NRST: MCU_IOs (C15.2 CN1.12 U1.24), Supply (CN3.12)

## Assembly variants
Highband: not fitted C1 CN3 R2 R3 R4 R5 SB2 SB7 SB8 SB11 SB12 SB13 SB18 SB21 SB22 SB23 SB24 SB25 SB27 SB28 SB29 SB30 SB32 SB33 SB34 SB35 SB37 SB38 SB39 SB41 SB43; alternate parts C2 -> MCD-03643, ANT1 -> MCD-03598
Lowband: not fitted C1 C2 C11 CN3 R2 R3 R4 R5 SB2 SB7 SB8 SB11 SB12 SB13 SB18 SB21 SB22 SB23 SB24 SB25 SB27 SB28 SB29 SB30 SB32 SB33 SB34 SB35 SB37 SB38 SB39 SB41 SB43; alternate parts L3 -> MCD-03470, L2 -> MCD-01766, U2 -> MCD-03964, ANT1 -> MCD-03599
